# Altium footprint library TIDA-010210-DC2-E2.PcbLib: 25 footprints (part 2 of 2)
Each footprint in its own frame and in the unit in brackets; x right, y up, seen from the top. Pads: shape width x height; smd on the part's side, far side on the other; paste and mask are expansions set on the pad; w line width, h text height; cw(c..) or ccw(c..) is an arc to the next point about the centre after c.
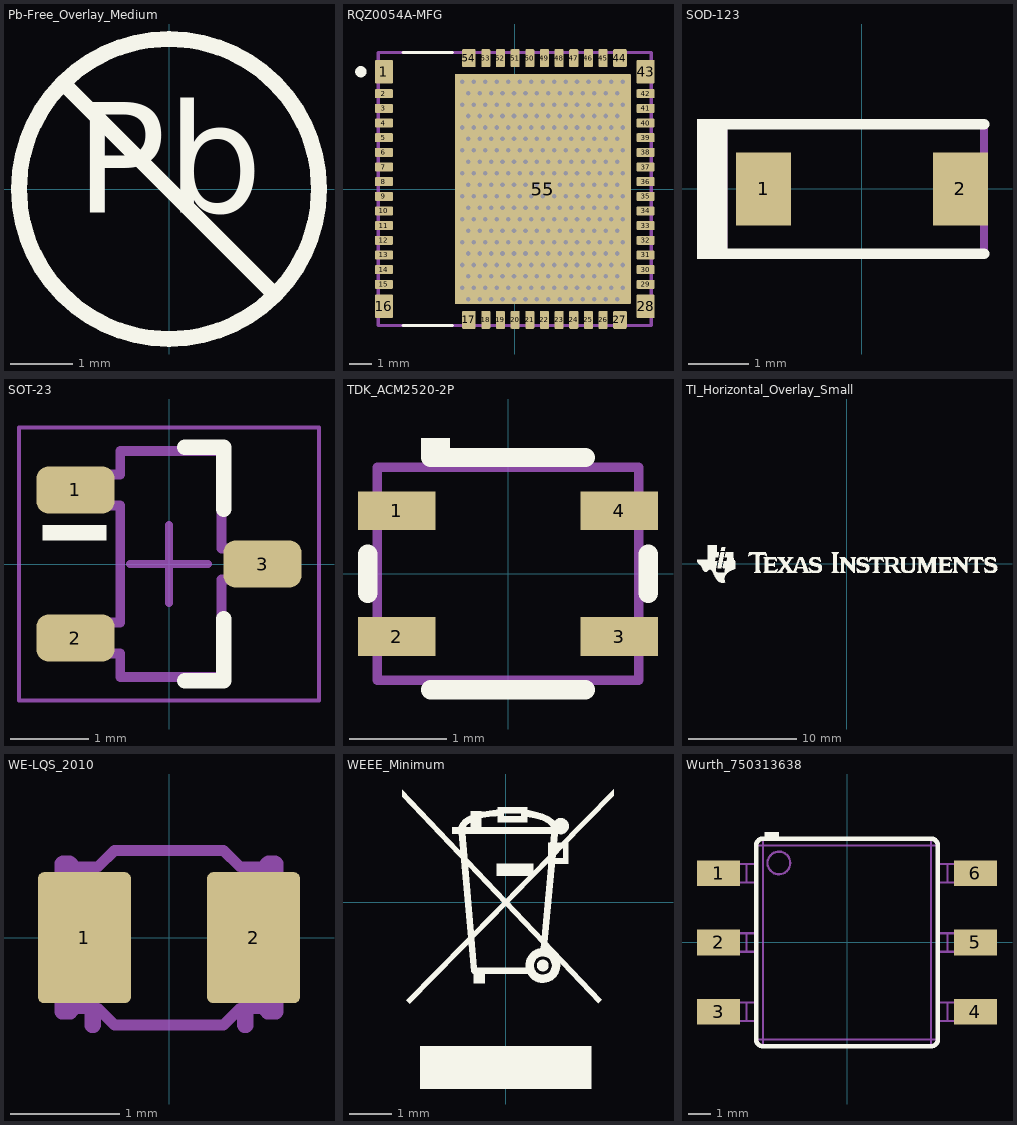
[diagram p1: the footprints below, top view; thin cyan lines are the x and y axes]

## Pb-Free_Overlay_Medium [mm]
height 27
Top Overlay:
  circle w0.254: c0,0 r2.413
  lines w0.254: -1.706,1.706 1.706,-1.706
  text "Pb" at -1.505,-0.961 h3.05

## RQZ0054A-MFG [mm]
height 19.4
pads (55):
  rrect13% 0.8x1.05 smd paste+0 mask+0: 1(-5.8,5.2) 16(-5.8,-5.2) 28(5.8,-5.2) 43(5.8,5.2)
  rrect25% 0.8x0.4 smd paste+0 mask+0: 2(-5.8,4.225) 3(-5.8,3.575) 4(-5.8,2.925) 5(-5.8,2.275) 6(-5.8,1.625) 7(-5.8,0.975) 8(-5.8,0.325) 9(-5.8,-0.325) 10(-5.8,-0.975) 11(-5.8,-1.625) 12(-5.8,-2.275) 13(-5.8,-2.925) 14(-5.8,-3.575) 15(-5.8,-4.225) 29(5.8,-4.225) 30(5.8,-3.575) 31(5.8,-2.925) 32(5.8,-2.275) 33(5.8,-1.625) 34(5.8,-0.975) 35(5.8,-0.325) 36(5.8,0.325) 37(5.8,0.975) 38(5.8,1.625) 39(5.8,2.275) 40(5.8,2.925) 41(5.8,3.575) 42(5.8,4.225)
  rrect17% 0.6x0.8 smd paste+0 mask+0: 17(-2.035,-5.8) 27(4.665,-5.8) 44(4.665,5.8) 54(-2.035,5.8)
  rrect25% 0.4x0.8 smd paste+0 mask+0: 18(-1.285,-5.8) 19(-0.635,-5.8) 20(0.015,-5.8) 21(0.665,-5.8) 22(1.315,-5.8) 23(1.965,-5.8) 24(2.615,-5.8) 25(3.265,-5.8) 26(3.915,-5.8) 45(3.915,5.8) 46(3.265,5.8) 47(2.615,5.8) 48(1.965,5.8) 49(1.315,5.8) 50(0.665,5.8) 51(0.015,5.8) 52(-0.635,5.8) 53(-1.285,5.8)
  rrect1% 7.8x10.2 smd paste-1000 mask+0: 55(1.25,0)
via -2.32,3.744 diameter 0.406 hole 0.203
via -1.812,3.744 diameter 0.406 hole 0.203
via -1.304,3.744 diameter 0.406 hole 0.203
via -0.796,3.744 diameter 0.406 hole 0.203
via -0.288,3.744 diameter 0.406 hole 0.203
via 0.22,3.744 diameter 0.406 hole 0.203
via 0.728,3.744 diameter 0.406 hole 0.203
via 3.776,3.744 diameter 0.406 hole 0.203
via 3.268,3.744 diameter 0.406 hole 0.203
via 2.76,3.744 diameter 0.406 hole 0.203
via 2.252,3.744 diameter 0.406 hole 0.203
via 1.744,3.744 diameter 0.406 hole 0.203
via 1.236,3.744 diameter 0.406 hole 0.203
via 4.792,3.744 diameter 0.406 hole 0.203
via 4.284,3.744 diameter 0.406 hole 0.203
via -2.066,4.252 diameter 0.406 hole 0.203
via -1.558,4.252 diameter 0.406 hole 0.203
via -1.05,4.252 diameter 0.406 hole 0.203
via -0.542,4.252 diameter 0.406 hole 0.203
via -0.034,4.252 diameter 0.406 hole 0.203
via 0.474,4.252 diameter 0.406 hole 0.203
via 0.982,4.252 diameter 0.406 hole 0.203
via 4.03,4.252 diameter 0.406 hole 0.203
via 3.522,4.252 diameter 0.406 hole 0.203
via 3.014,4.252 diameter 0.406 hole 0.203
via 2.506,4.252 diameter 0.406 hole 0.203
via 1.998,4.252 diameter 0.406 hole 0.203
via 1.49,4.252 diameter 0.406 hole 0.203
via 4.538,4.252 diameter 0.406 hole 0.203
via 4.284,4.76 diameter 0.406 hole 0.203
via 4.792,4.76 diameter 0.406 hole 0.203
via 1.236,4.76 diameter 0.406 hole 0.203
via 1.744,4.76 diameter 0.406 hole 0.203
via 2.252,4.76 diameter 0.406 hole 0.203
via 2.76,4.76 diameter 0.406 hole 0.203
via 3.268,4.76 diameter 0.406 hole 0.203
via 3.776,4.76 diameter 0.406 hole 0.203
via 0.728,4.76 diameter 0.406 hole 0.203
via 0.22,4.76 diameter 0.406 hole 0.203
via -0.288,4.76 diameter 0.406 hole 0.203
via -0.796,4.76 diameter 0.406 hole 0.203
via -1.304,4.76 diameter 0.406 hole 0.203
via -1.812,4.76 diameter 0.406 hole 0.203
via -2.32,4.76 diameter 0.406 hole 0.203
via 4.538,3.236 diameter 0.406 hole 0.203
via 1.49,3.236 diameter 0.406 hole 0.203
via 1.998,3.236 diameter 0.406 hole 0.203
via 2.506,3.236 diameter 0.406 hole 0.203
via 3.014,3.236 diameter 0.406 hole 0.203
via 3.522,3.236 diameter 0.406 hole 0.203
via 4.03,3.236 diameter 0.406 hole 0.203
via 0.982,3.236 diameter 0.406 hole 0.203
via 0.474,3.236 diameter 0.406 hole 0.203
via -0.034,3.236 diameter 0.406 hole 0.203
via -0.542,3.236 diameter 0.406 hole 0.203
via -1.05,3.236 diameter 0.406 hole 0.203
via -1.558,3.236 diameter 0.406 hole 0.203
via -2.066,3.236 diameter 0.406 hole 0.203
via 4.284,2.728 diameter 0.406 hole 0.203
via 4.792,2.728 diameter 0.406 hole 0.203
via 1.236,2.728 diameter 0.406 hole 0.203
via 1.744,2.728 diameter 0.406 hole 0.203
via 2.252,2.728 diameter 0.406 hole 0.203
via 2.76,2.728 diameter 0.406 hole 0.203
via 3.268,2.728 diameter 0.406 hole 0.203
via 3.776,2.728 diameter 0.406 hole 0.203
via 0.728,2.728 diameter 0.406 hole 0.203
via 0.22,2.728 diameter 0.406 hole 0.203
via -0.288,2.728 diameter 0.406 hole 0.203
via -0.796,2.728 diameter 0.406 hole 0.203
via -1.304,2.728 diameter 0.406 hole 0.203
via -1.812,2.728 diameter 0.406 hole 0.203
via -2.32,2.728 diameter 0.406 hole 0.203
via 4.538,2.22 diameter 0.406 hole 0.203
via 1.49,2.22 diameter 0.406 hole 0.203
via 1.998,2.22 diameter 0.406 hole 0.203
via 2.506,2.22 diameter 0.406 hole 0.203
via 3.014,2.22 diameter 0.406 hole 0.203
via 3.522,2.22 diameter 0.406 hole 0.203
via 4.03,2.22 diameter 0.406 hole 0.203
via 0.982,2.22 diameter 0.406 hole 0.203
via 0.474,2.22 diameter 0.406 hole 0.203
via -0.034,2.22 diameter 0.406 hole 0.203
via -0.542,2.22 diameter 0.406 hole 0.203
via -1.05,2.22 diameter 0.406 hole 0.203
via -1.558,2.22 diameter 0.406 hole 0.203
via -2.066,2.22 diameter 0.406 hole 0.203
via 4.284,1.712 diameter 0.406 hole 0.203
via 4.792,1.712 diameter 0.406 hole 0.203
via 1.236,1.712 diameter 0.406 hole 0.203
via 1.744,1.712 diameter 0.406 hole 0.203
via 2.252,1.712 diameter 0.406 hole 0.203
via 2.76,1.712 diameter 0.406 hole 0.203
via 3.268,1.712 diameter 0.406 hole 0.203
via 3.776,1.712 diameter 0.406 hole 0.203
via 0.728,1.712 diameter 0.406 hole 0.203
via 0.22,1.712 diameter 0.406 hole 0.203
via -0.288,1.712 diameter 0.406 hole 0.203
via -0.796,1.712 diameter 0.406 hole 0.203
via -1.304,1.712 diameter 0.406 hole 0.203
via -1.812,1.712 diameter 0.406 hole 0.203
via -2.32,1.712 diameter 0.406 hole 0.203
via 4.538,1.204 diameter 0.406 hole 0.203
via 1.49,1.204 diameter 0.406 hole 0.203
via 1.998,1.204 diameter 0.406 hole 0.203
via 2.506,1.204 diameter 0.406 hole 0.203
via 3.014,1.204 diameter 0.406 hole 0.203
via 3.522,1.204 diameter 0.406 hole 0.203
via 4.03,1.204 diameter 0.406 hole 0.203
via 0.982,1.204 diameter 0.406 hole 0.203
via 0.474,1.204 diameter 0.406 hole 0.203
via -0.034,1.204 diameter 0.406 hole 0.203
via -0.542,1.204 diameter 0.406 hole 0.203
via -1.05,1.204 diameter 0.406 hole 0.203
via -1.558,1.204 diameter 0.406 hole 0.203
via -2.066,1.204 diameter 0.406 hole 0.203
via 4.284,0.696 diameter 0.406 hole 0.203
via 4.792,0.696 diameter 0.406 hole 0.203
via 1.236,0.696 diameter 0.406 hole 0.203
via 1.744,0.696 diameter 0.406 hole 0.203
via 2.252,0.696 diameter 0.406 hole 0.203
via 2.76,0.696 diameter 0.406 hole 0.203
via 3.268,0.696 diameter 0.406 hole 0.203
via 3.776,0.696 diameter 0.406 hole 0.203
via 0.728,0.696 diameter 0.406 hole 0.203
via 0.22,0.696 diameter 0.406 hole 0.203
via -0.288,0.696 diameter 0.406 hole 0.203
via -0.796,0.696 diameter 0.406 hole 0.203
via -1.304,0.696 diameter 0.406 hole 0.203
via -1.812,0.696 diameter 0.406 hole 0.203
via -2.32,0.696 diameter 0.406 hole 0.203
via 4.538,0.188 diameter 0.406 hole 0.203
via 1.49,0.188 diameter 0.406 hole 0.203
via 1.998,0.188 diameter 0.406 hole 0.203
via 2.506,0.188 diameter 0.406 hole 0.203
via 3.014,0.188 diameter 0.406 hole 0.203
via 3.522,0.188 diameter 0.406 hole 0.203
via 4.03,0.188 diameter 0.406 hole 0.203
via 0.982,0.188 diameter 0.406 hole 0.203
via 0.474,0.188 diameter 0.406 hole 0.203
via -0.034,0.188 diameter 0.406 hole 0.203
via -0.542,0.188 diameter 0.406 hole 0.203
via -1.05,0.188 diameter 0.406 hole 0.203
via -1.558,0.188 diameter 0.406 hole 0.203
via -2.066,0.188 diameter 0.406 hole 0.203
via 4.284,-0.32 diameter 0.406 hole 0.203
via 4.792,-0.32 diameter 0.406 hole 0.203
via 1.236,-0.32 diameter 0.406 hole 0.203
via 1.744,-0.32 diameter 0.406 hole 0.203
via 2.252,-0.32 diameter 0.406 hole 0.203
via 2.76,-0.32 diameter 0.406 hole 0.203
via 3.268,-0.32 diameter 0.406 hole 0.203
via 3.776,-0.32 diameter 0.406 hole 0.203
via 0.728,-0.32 diameter 0.406 hole 0.203
via 0.22,-0.32 diameter 0.406 hole 0.203
via -0.288,-0.32 diameter 0.406 hole 0.203
via -0.796,-0.32 diameter 0.406 hole 0.203
via -1.304,-0.32 diameter 0.406 hole 0.203
via -1.812,-0.32 diameter 0.406 hole 0.203
via -2.32,-0.32 diameter 0.406 hole 0.203
via 4.538,-0.828 diameter 0.406 hole 0.203
via 1.49,-0.828 diameter 0.406 hole 0.203
via 1.998,-0.828 diameter 0.406 hole 0.203
via 2.506,-0.828 diameter 0.406 hole 0.203
via 3.014,-0.828 diameter 0.406 hole 0.203
via 3.522,-0.828 diameter 0.406 hole 0.203
via 4.03,-0.828 diameter 0.406 hole 0.203
via 0.982,-0.828 diameter 0.406 hole 0.203
via 0.474,-0.828 diameter 0.406 hole 0.203
via -0.034,-0.828 diameter 0.406 hole 0.203
via -0.542,-0.828 diameter 0.406 hole 0.203
via -1.05,-0.828 diameter 0.406 hole 0.203
via -1.558,-0.828 diameter 0.406 hole 0.203
via -2.066,-0.828 diameter 0.406 hole 0.203
via 4.284,-1.336 diameter 0.406 hole 0.203
via 4.792,-1.336 diameter 0.406 hole 0.203
via 1.236,-1.336 diameter 0.406 hole 0.203
via 1.744,-1.336 diameter 0.406 hole 0.203
via 2.252,-1.336 diameter 0.406 hole 0.203
via 2.76,-1.336 diameter 0.406 hole 0.203
via 3.268,-1.336 diameter 0.406 hole 0.203
via 3.776,-1.336 diameter 0.406 hole 0.203
via 0.728,-1.336 diameter 0.406 hole 0.203
via 0.22,-1.336 diameter 0.406 hole 0.203
via -0.288,-1.336 diameter 0.406 hole 0.203
via -0.796,-1.336 diameter 0.406 hole 0.203
via -1.304,-1.336 diameter 0.406 hole 0.203
via -1.812,-1.336 diameter 0.406 hole 0.203
via -2.32,-1.336 diameter 0.406 hole 0.203
via 4.538,-1.844 diameter 0.406 hole 0.203
via 1.49,-1.844 diameter 0.406 hole 0.203
via 1.998,-1.844 diameter 0.406 hole 0.203
via 2.506,-1.844 diameter 0.406 hole 0.203
via 3.014,-1.844 diameter 0.406 hole 0.203
via 3.522,-1.844 diameter 0.406 hole 0.203
via 4.03,-1.844 diameter 0.406 hole 0.203
via 0.982,-1.844 diameter 0.406 hole 0.203
via 0.474,-1.844 diameter 0.406 hole 0.203
via -0.034,-1.844 diameter 0.406 hole 0.203
via -0.542,-1.844 diameter 0.406 hole 0.203
via -1.05,-1.844 diameter 0.406 hole 0.203
via -1.558,-1.844 diameter 0.406 hole 0.203
via -2.066,-1.844 diameter 0.406 hole 0.203
via 4.284,-2.352 diameter 0.406 hole 0.203
via 4.792,-2.352 diameter 0.406 hole 0.203
via 1.236,-2.352 diameter 0.406 hole 0.203
via 1.744,-2.352 diameter 0.406 hole 0.203
via 2.252,-2.352 diameter 0.406 hole 0.203
via 2.76,-2.352 diameter 0.406 hole 0.203
via 3.268,-2.352 diameter 0.406 hole 0.203
via 3.776,-2.352 diameter 0.406 hole 0.203
via 0.728,-2.352 diameter 0.406 hole 0.203
via 0.22,-2.352 diameter 0.406 hole 0.203
via -0.288,-2.352 diameter 0.406 hole 0.203
via -0.796,-2.352 diameter 0.406 hole 0.203
via -1.304,-2.352 diameter 0.406 hole 0.203
via -1.812,-2.352 diameter 0.406 hole 0.203
via -2.32,-2.352 diameter 0.406 hole 0.203
via 4.538,-2.86 diameter 0.406 hole 0.203
via 1.49,-2.86 diameter 0.406 hole 0.203
via 1.998,-2.86 diameter 0.406 hole 0.203
via 2.506,-2.86 diameter 0.406 hole 0.203
via 3.014,-2.86 diameter 0.406 hole 0.203
via 3.522,-2.86 diameter 0.406 hole 0.203
via 4.03,-2.86 diameter 0.406 hole 0.203
via 0.982,-2.86 diameter 0.406 hole 0.203
via 0.474,-2.86 diameter 0.406 hole 0.203
via -0.034,-2.86 diameter 0.406 hole 0.203
via -0.542,-2.86 diameter 0.406 hole 0.203
via -1.05,-2.86 diameter 0.406 hole 0.203
via -1.558,-2.86 diameter 0.406 hole 0.203
via -2.066,-2.86 diameter 0.406 hole 0.203
via 4.284,-3.368 diameter 0.406 hole 0.203
via 4.792,-3.368 diameter 0.406 hole 0.203
via 1.236,-3.368 diameter 0.406 hole 0.203
via 1.744,-3.368 diameter 0.406 hole 0.203
via 2.252,-3.368 diameter 0.406 hole 0.203
via 2.76,-3.368 diameter 0.406 hole 0.203
via 3.268,-3.368 diameter 0.406 hole 0.203
via 3.776,-3.368 diameter 0.406 hole 0.203
via 0.728,-3.368 diameter 0.406 hole 0.203
via 0.22,-3.368 diameter 0.406 hole 0.203
via -0.288,-3.368 diameter 0.406 hole 0.203
via -0.796,-3.368 diameter 0.406 hole 0.203
via -1.304,-3.368 diameter 0.406 hole 0.203
via -1.812,-3.368 diameter 0.406 hole 0.203
via -2.32,-3.368 diameter 0.406 hole 0.203
via 4.538,-3.876 diameter 0.406 hole 0.203
via 1.49,-3.876 diameter 0.406 hole 0.203
via 1.998,-3.876 diameter 0.406 hole 0.203
via 2.506,-3.876 diameter 0.406 hole 0.203
via 3.014,-3.876 diameter 0.406 hole 0.203
via 3.522,-3.876 diameter 0.406 hole 0.203
via 4.03,-3.876 diameter 0.406 hole 0.203
via 0.982,-3.876 diameter 0.406 hole 0.203
via 0.474,-3.876 diameter 0.406 hole 0.203
via -0.034,-3.876 diameter 0.406 hole 0.203
via -0.542,-3.876 diameter 0.406 hole 0.203
via -1.05,-3.876 diameter 0.406 hole 0.203
via -1.558,-3.876 diameter 0.406 hole 0.203
via -2.066,-3.876 diameter 0.406 hole 0.203
via 4.284,-4.384 diameter 0.406 hole 0.203
via 4.792,-4.384 diameter 0.406 hole 0.203
via 1.236,-4.384 diameter 0.406 hole 0.203
via 1.744,-4.384 diameter 0.406 hole 0.203
via 2.252,-4.384 diameter 0.406 hole 0.203
via 2.76,-4.384 diameter 0.406 hole 0.203
via 3.268,-4.384 diameter 0.406 hole 0.203
via 3.776,-4.384 diameter 0.406 hole 0.203
via 0.728,-4.384 diameter 0.406 hole 0.203
via 0.22,-4.384 diameter 0.406 hole 0.203
via -0.288,-4.384 diameter 0.406 hole 0.203
via -0.796,-4.384 diameter 0.406 hole 0.203
via -1.304,-4.384 diameter 0.406 hole 0.203
via -1.812,-4.384 diameter 0.406 hole 0.203
via -2.32,-4.384 diameter 0.406 hole 0.203
via 4.538,-4.892 diameter 0.406 hole 0.203
via 1.49,-4.892 diameter 0.406 hole 0.203
via 1.998,-4.892 diameter 0.406 hole 0.203
via 2.506,-4.892 diameter 0.406 hole 0.203
via 3.014,-4.892 diameter 0.406 hole 0.203
via 3.522,-4.892 diameter 0.406 hole 0.203
via 4.03,-4.892 diameter 0.406 hole 0.203
via 0.982,-4.892 diameter 0.406 hole 0.203
via 0.474,-4.892 diameter 0.406 hole 0.203
via -0.034,-4.892 diameter 0.406 hole 0.203
via -0.542,-4.892 diameter 0.406 hole 0.203
via -1.05,-4.892 diameter 0.406 hole 0.203
via -1.558,-4.892 diameter 0.406 hole 0.203
via -2.066,-4.892 diameter 0.406 hole 0.203
Top Overlay:
  circle w0.25: c-6.825,5.2 r0.125
  lines w0.15: -4.955,-6.05 -2.78,-6.05 ; -4.955,6.05 -2.78,6.05
Top Paste:
  drawing of 48 lines, arcs and shapes, not listed
Mechanical 5:
  lines w0.15: -6.05,-6.05 6.05,-6.05 6.05,6.05 -6.05,6.05 -6.05,-6.05
  text ".Designator" at 0,0 h0.5
3D body "IC_LMG3425R050RQZT_VQFN54.STEP": height 0.9, standoff 0, extent -6,-6 6,6

## SOD-123 [mm] "On Semi recommended land pattern"
height 1.35
pads (2):
  rect 0.915x1.22 smd: 1(-1.637,0) 2(1.637,0)
Top Overlay:
  rectangle: -2.744,-1.169 -2.236,1.168
  lines w0.178: -2.413,-1.079 2.032,-1.079 ; -2.413,1.079 2.032,1.079
Mechanical 5:
  rectangle: -2.744,-1.169 -2.236,1.168
  lines w0.127: -2.413,-1.079 2.032,-1.079 2.032,1.079 -2.413,1.079
  text ".Designator" at -0.533,0.406 h0.46
3D body "SOD-123.stp": height 1.35, standoff 0, extent -1.932,-0.9 1.932,0.9

## SOT-23 [mm] "SOT23, 3-Leads, Body 2.9x1.3mm, Pitch 0.95mm, Lead Span 2.5mm, IPC Medium Density"
height 1.1
pads (3):
  rrect50% 1x0.6 smd: 1(-1.2,0.95) 2(-1.2,-0.95) 3(1.2,0)
Top Overlay:
  rectangle: -1.625,0.3 -0.8,0.5
  lines w0.2: 0.2,-1.5 0.7,-1.5 0.7,-0.7 ; 0.2,1.5 0.7,1.5 0.7,0.7
Mechanical 5:
  lines w0.127: -1.16,-1.15 -0.625,-1.15 -0.625,-1.45 0.675,-1.45 0.675,-0.2 1.21,-0.2 1.21,0.2 0.675,0.2 0.675,1.45 -0.625,1.45 -0.625,1.15 -1.16,1.15 -1.16,0.75 -0.625,0.75 -0.625,-0.75 -1.16,-0.75 -1.16,-1.15
  text ".Designator" at -0.267,0.076 h0.46
Mechanical 15:
  lines w0.05: -1.925,-1.75 -1.925,1.75 1.925,1.75 1.925,-1.75 -1.925,-1.75
  lines w0.1: -0.5,0 0.5,0 ; 0,-0.5 0,0.5
3D body "SW3dPS-sot-3p290x130ll237h100.STEP": height 1, standoff 0, extent -1.16,-1.45 1.21,1.45

## TDK_ACM2520-2P [mm] "SMD, 4-Leads, Body 2.5x2mm"
height 1.3
pads (4):
  rect 0.8x0.4 smd: 1(-1.15,0.65) 2(-1.15,-0.65) 3(1.15,-0.65) 4(1.15,0.65)
Top Overlay:
  rectangle: -0.9,1.2 -0.6,1.4
  lines w0.2: -0.8,-1.2 0.8,-1.2 ; -0.8,1.2 0.8,1.2
  lines w0.203: -1.45,-0.2 -1.45,0.2 ; 1.45,-0.2 1.45,0.2
Mechanical 5:
  lines w0.1: -1.35,-1.1 1.35,-1.1 1.35,1.1 -1.35,1.1 -1.35,-1.1
  text ".Designator" at 0.334,-0.356 h0.46
3D body: height 1.3, standoff 0, extent -1.349,-1.099 1.349,1.099

## TI_Horizontal_Overlay_Small [mm]
height 19.05
Top Overlay:
  drawing of 18 lines, arcs and shapes, not listed

## WE-LQS_2010 [mm] "SMD, 2-Leads, Body 2x1.6mm"
height 1
pads (2):
  rrect12% 0.85x1.2 smd: 1(-0.775,0) 2(0.775,0)
Mechanical 5:
  drawing of 345 lines, arcs and shapes, not listed
  text ".Designator" at 0.456,0.254 h0.46
3D body "WE-LQS_2010.stp": height 0.98, standoff -0.02, extent -1,-0.824 1,0.8

## WEEE_Minimum [mm] "WEEElie bin"
height 19.05
Top Overlay:
  drawing of 23 lines, arcs and shapes, not listed

## Wurth_750313638 [mm] "SMD, 6-Leads, Body 8x9.14mm, Pitch 3.05mm"
height 7.62
pads (6):
  rect 1.9x1.14 smd: 1(-5.655,3.05) 2(-5.655,0) 3(-5.655,-3.05) 4(5.655,-3.05) 5(5.655,0) 6(5.655,3.05)
Top Overlay:
  rectangle: -3.625,4.57 -3,4.875
  lines w0.2: -4,-4.27 ccw(c-3.7,-4.27) -3.7,-4.57 3.7,-4.57 ccw(c3.7,-4.27) 4,-4.27 4,4.27 ccw(c3.7,4.27) 3.7,4.57 -3.7,4.57 ccw(c-3.7,4.27) -4,4.27 -4,-4.27
Mechanical 5:
  circle w0.1: c-3,3.5 r0.5
  lines w0.1: -4,-3.455 -4.43,-3.455 ; -4,-2.645 -4.43,-2.645 ; -4,-0.405 -4.43,-0.405 ; -4,0.405 -4.43,0.405 ; -4,2.645 -4.43,2.645 ; -4,3.455 -4.43,3.455 ; 4,-3.455 4.43,-3.455 ; 4,-2.645 4.43,-2.645 ; 4,-0.405 4.43,-0.405 ; 4,0.405 4.43,0.405 ; 4,2.645 4.43,2.645 ; 4,3.455 4.43,3.455 ; -5.47,-3.455 -5.47,-2.645 ; -5.47,-3.455 -6.35,-3.455 -6.35,-2.645 -5.47,-2.645 ; -5.47,-3.455 -5.376,-3.455 ; -5.47,-2.645 -5.376,-2.645 ; -5.47,-0.405 -5.47,0.405 ; -5.47,-0.405 -5.376,-0.405 ; -5.47,-0.405 -6.35,-0.405 -6.35,0.405 -5.47,0.405 ; -5.47,0.405 -5.376,0.405 ; -5.47,2.645 -5.47,3.455 ; -5.47,2.645 -6.35,2.645 -6.35,3.455 -5.47,3.455 ; -5.47,2.645 -5.376,2.645 ; -5.47,3.455 -5.376,3.455 ; -5.376,-3.455 -5.376,-2.645 ; -5.376,-3.455 -4.9,-3.455 ; -5.376,-2.645 -4.9,-2.645 ; -5.376,-0.405 -5.376,0.405 ; -5.376,-0.405 -4.9,-0.405 ; -5.376,0.405 -4.9,0.405 ; -5.376,2.645 -5.376,3.455 ; -5.376,2.645 -4.9,2.645 ; -5.376,3.455 -4.9,3.455 ; -4.9,-3.455 -4.9,-2.645 ; -4.9,-3.455 -4.43,-3.455 ; -4.9,-2.645 -4.43,-2.645 ; -4.9,-0.405 -4.9,0.405 ; -4.9,-0.405 -4.43,-0.405 ; -4.9,0.405 -4.43,0.405 ; -4.9,2.645 -4.9,3.455 ; -4.9,2.645 -4.43,2.645 ; -4.9,3.455 -4.43,3.455 ; -4.43,-3.455 -4.43,-2.645 ; -4.43,-0.405 -4.43,0.405 ; -4.43,2.645 -4.43,3.455 ; -4,-4.27 ccw(c-3.7,-4.27) -3.7,-4.57 ; -4,-4.27 -3.7,-4.27 ; -4,-4.27 -4,4.27 ; -4,4.27 cw(c-3.7,4.27) -3.7,4.57 ; -4,4.27 -3.7,4.27 ; -3.7,-4.57 -3.7,-4.27 ; -3.7,-4.57 3.7,-4.57 ; -3.7,-4.27 3.7,-4.27 ; -3.7,-4.27 -3.7,4.27 ; -3.7,4.27 -3.7,4.57 ; -3.7,4.27 3.7,4.27 ; -3.7,4.57 3.7,4.57 ; 3.7,-4.57 ccw(c3.7,-4.27) 4,-4.27 ; 3.7,-4.57 3.7,-4.27 ; 3.7,-4.27 4,-4.27 ; 3.7,-4.27 3.7,4.27 ; 3.7,4.27 4,4.27 ; 3.7,4.27 3.7,4.57 ; 3.7,4.57 cw(c3.7,4.27) 4,4.27 ; 4,-4.27 4,4.27 ; 4.43,-3.455 4.43,-2.645 ; 4.43,-3.455 4.9,-3.455 ; 4.43,-2.645 4.9,-2.645 ; 4.43,-0.405 4.43,0.405 ; 4.43,-0.405 4.9,-0.405 ; 4.43,0.405 4.9,0.405 ; 4.43,2.645 4.43,3.455 ; 4.43,2.645 4.9,2.645 ; 4.43,3.455 4.9,3.455 ; 4.9,-3.455 4.9,-2.645 ; 4.9,-3.455 5.376,-3.455 ; 4.9,-2.645 5.376,-2.645 ; 4.9,-0.405 4.9,0.405 ; 4.9,-0.405 5.376,-0.405 ; 4.9,0.405 5.376,0.405 ; 4.9,2.645 4.9,3.455 ; 4.9,2.645 5.376,2.645 ; 4.9,3.455 5.376,3.455 ; 5.376,-3.455 5.376,-2.645 ; 5.376,-3.455 5.47,-3.455 ; 5.376,-2.645 5.47,-2.645 ; 5.376,-0.405 5.376,0.405 ; 5.376,-0.405 5.47,-0.405 ; 5.376,0.405 5.47,0.405 ; 5.376,2.645 5.376,3.455 ; 5.376,2.645 5.47,2.645 ; 5.376,3.455 5.47,3.455 ; 5.47,-3.455 5.47,-2.645 ; 5.47,-3.455 6.35,-3.455 6.35,-2.645 5.47,-2.645 ; 5.47,-0.405 5.47,0.405 ; 5.47,-0.405 6.35,-0.405 6.35,0.405 5.47,0.405 ; 5.47,2.645 5.47,3.455 ; 5.47,2.645 6.35,2.645 6.35,3.455 5.47,3.455
  text ".Designator" at 0.697,0.007 h0.46
3D body "750313638.stp": height 7.62, standoff 0, extent -6.35,-4.57 6.35,4.57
